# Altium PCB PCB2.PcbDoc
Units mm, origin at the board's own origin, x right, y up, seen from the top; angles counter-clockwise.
Board outline 200 x 200.6 mm, 2 copper layers (Top Layer, Bottom Layer); 120 components, 153 nets, 524 pads, 0 vias.
Unrouted connection lines stored in the file: 336.
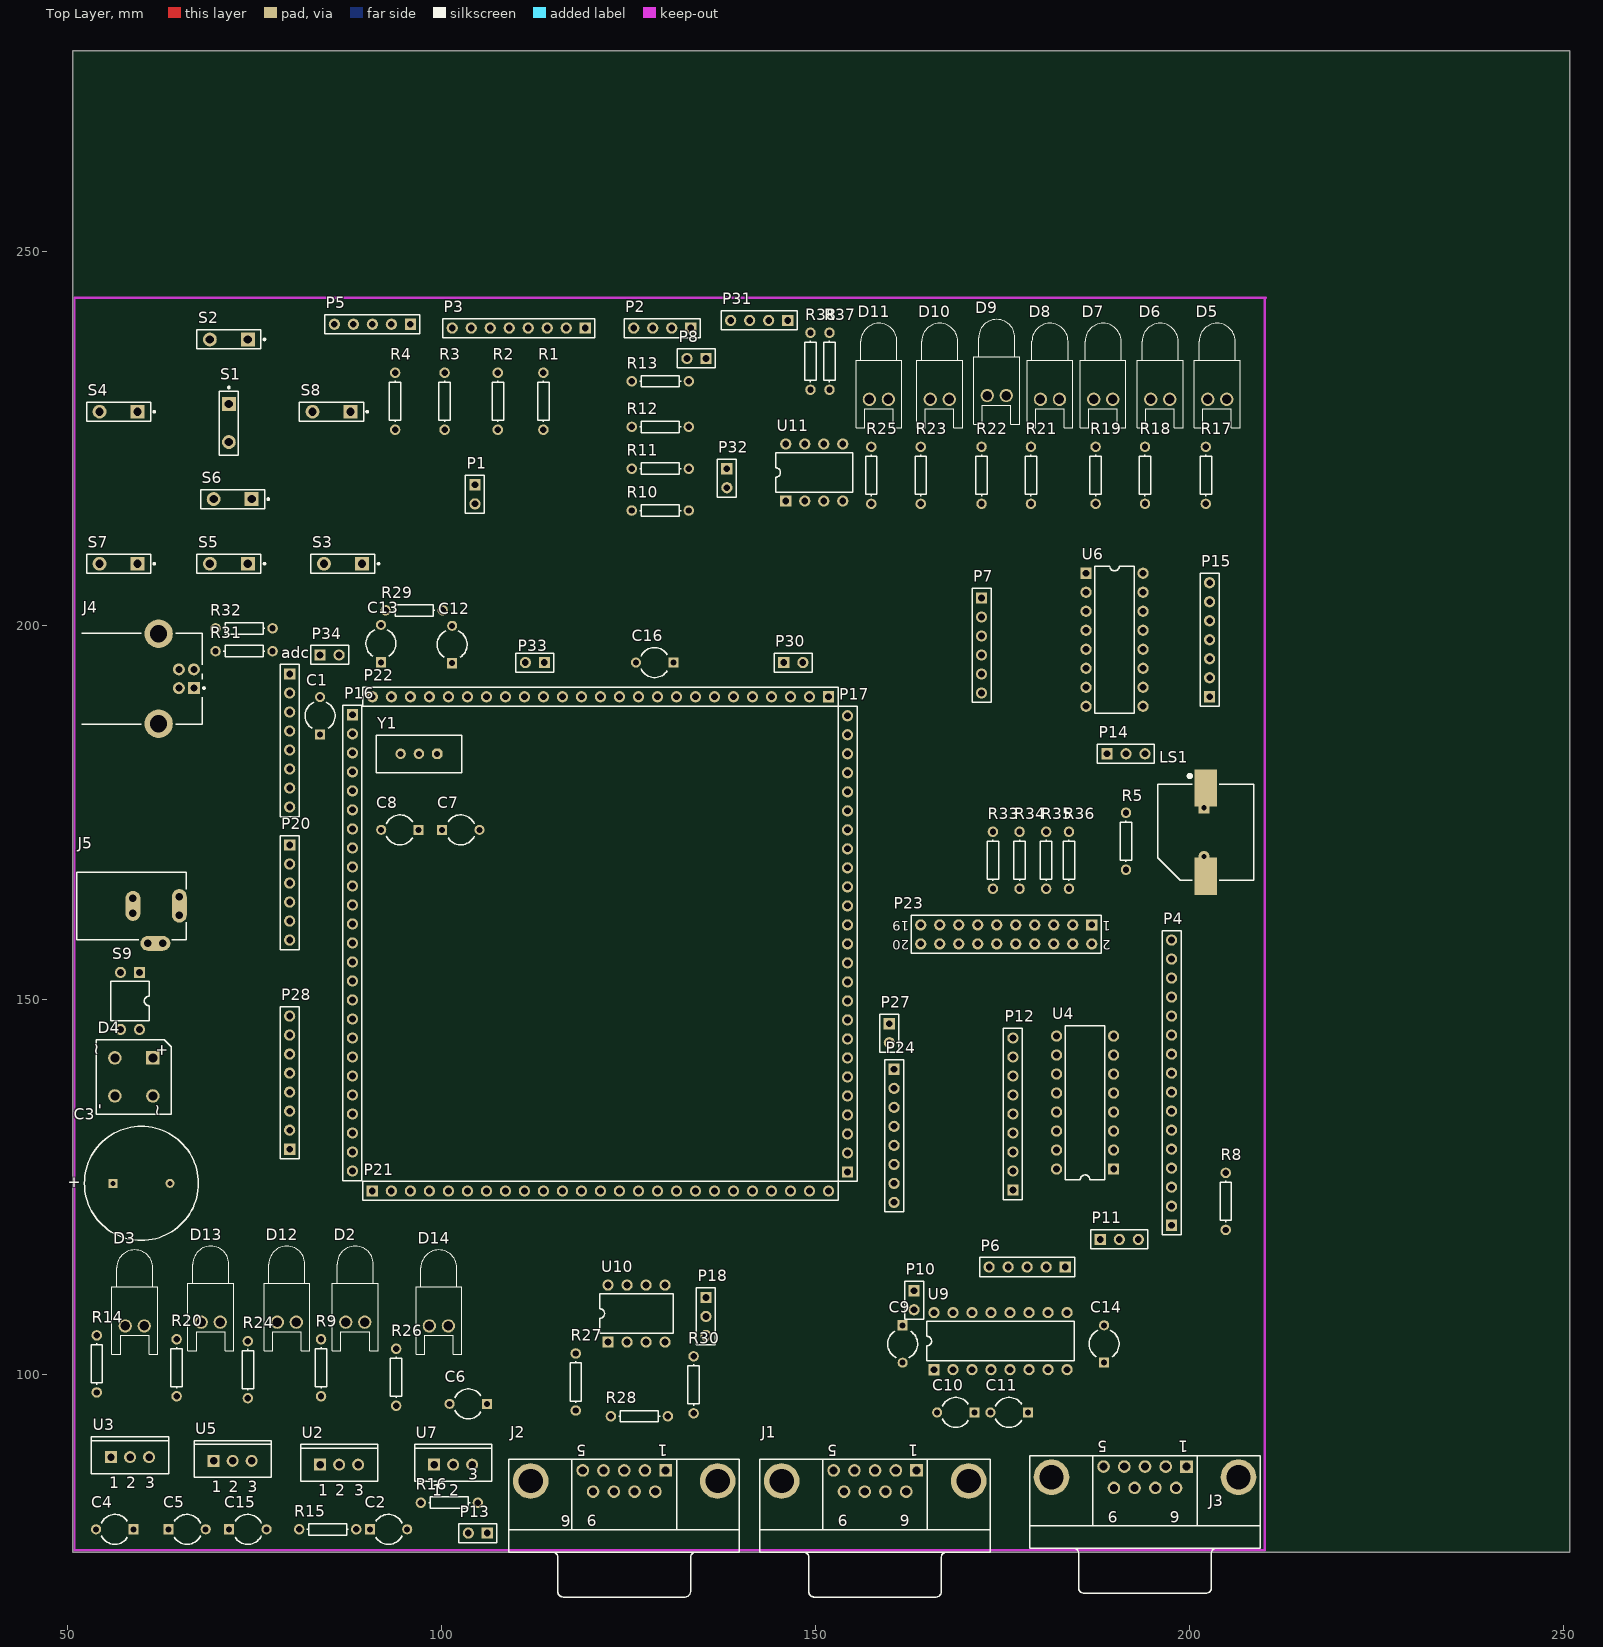
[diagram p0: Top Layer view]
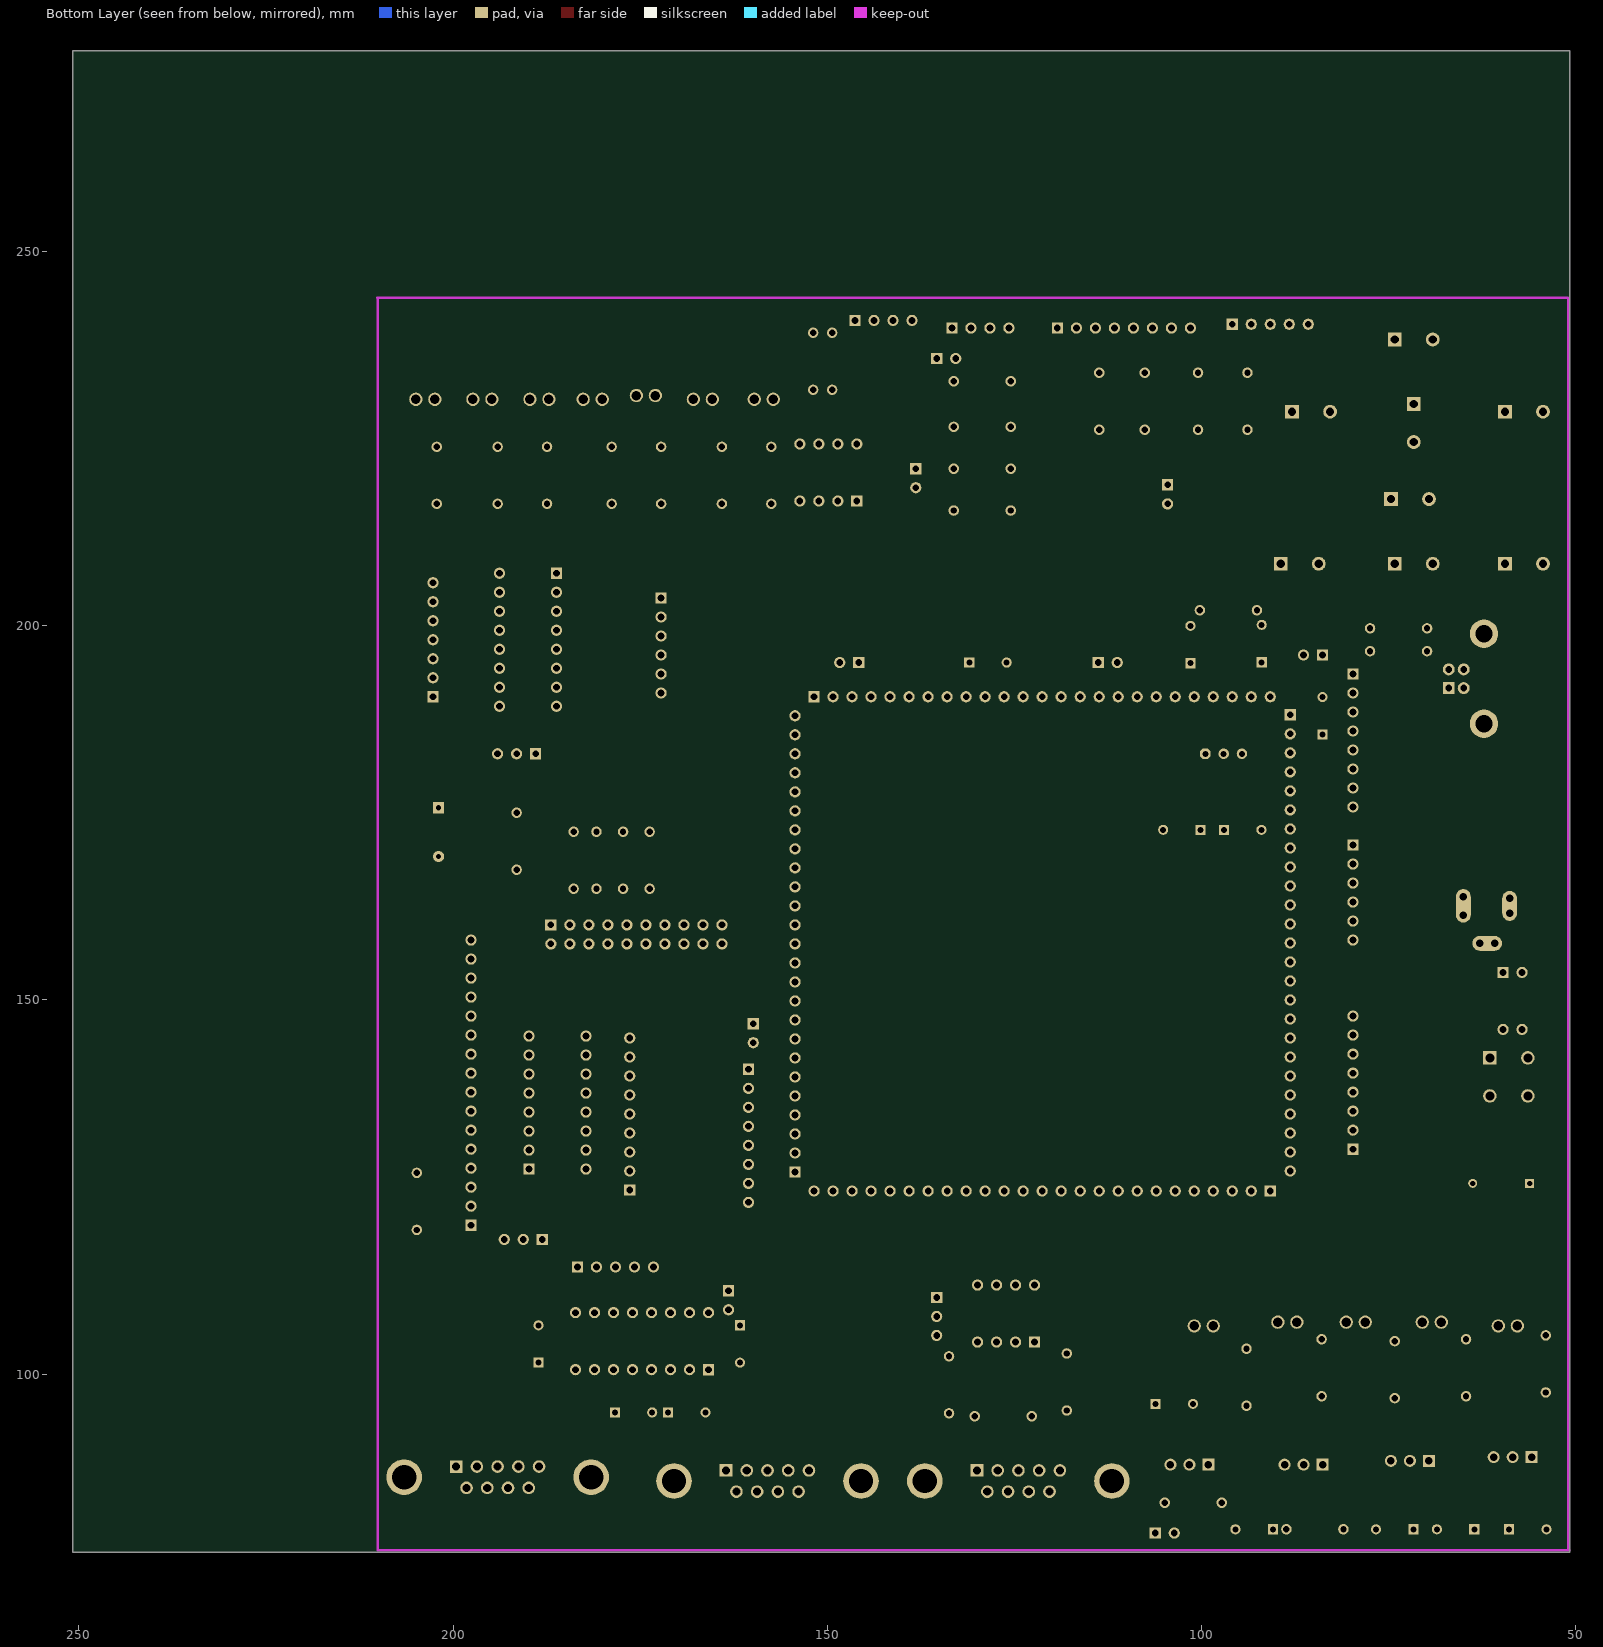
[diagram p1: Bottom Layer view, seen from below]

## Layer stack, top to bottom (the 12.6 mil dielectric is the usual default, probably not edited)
Top Layer: signal copper 0.0356
Dielectric: dielectric 0.32, FR-4, Dk 4.8
Bottom Layer: signal copper 0.0356

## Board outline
50.8,76.2 250.8,76.2 250.8,276.8 50.8,276.8

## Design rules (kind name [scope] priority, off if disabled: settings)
Clearance [All] p1: gap=0.2
PolygonConnect [All] p1: connectstyle=Relief reliefconductorwidth=0.254 reliefentries=4 polygonreliefangle="90 Angle"
RoomDefinition relevance [InComponentClass('relevance')] p1: confinementstyle=ConfineIn formatcopy=TRUE lockcomponents=FALSE outline 0,0 50.8,0 50.8,25.4 0,25.4
RoutingLayers [All] p1: top layer_v5=FALSE bottom layer_v5=TRUE
RoutingVias [All] p1: holewidth=0.2 width=2 viastyle="Through Hole" minholewidth=0.711 minwidth=1.27 maxholewidth=0.711 maxwidth=1.27
SilkscreenOverComponentPads [All] p1: minsilkscreentomaskgap=0.254
SolderMaskExpansion [All] p1: expansion=0.102
TestPointUsage [All] p1: valid=0 allowmultiple=FALSE
Testpoint [All] p1: side=15 testpointundercomponent=TRUE minsize=1.016 maxsize=2.54 preferedsize=1.524 minholesize=0 maxholesize=1.016 preferedholesize=0.813 testpointgrid=0.025 style=1023 order=0-112345678
Width [All] p1: maxlimit=0.2 minlimit=0.2 preferedwidth=0.2
22 further rules are at their usual default settings.

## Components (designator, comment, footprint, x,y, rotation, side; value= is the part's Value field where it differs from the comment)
adc "Header 8" HDR1X8 79.756,193.548 r270 top
C1 "Cap2" CAPR5-4X5 83.82,187.96 r90 top
C2 "Cap2" CAPR5-4X5 92.964,79.248 r0 top
C3 "Cap Pol1" RB7.6-15 59.944,125.476 r180 top
C4 "Cap2" CAPR5-4X5 56.388,79.248 r180 top
C5 "Cap2" CAPR5-4X5 66.04,79.248 r0 top
C6 "Cap2" CAPR5-4X5 103.632,96.012 r180 top
C7 "Cap2" CAPR5-4X5 102.616,172.72 r0 top
C8 "Cap2" CAPR5-4X5 94.488,172.72 r180 top
C9 "Cap2" CAPR5-4X5 161.671,104.013 r270 top
C10 "Cap2" CAPR5-4X5 168.783,94.869 r180 top
C11 "Cap2" CAPR5-4X5 175.895,94.869 r180 top
C12 "Cap2" CAPR5-4X5 101.473,197.485 r90 top
C13 "Cap2" CAPR5-4X5 91.948,197.612 r90 top
C14 "Cap2" CAPR5-4X5 188.595,104.013 r90 top
C15 "Cap2" CAPR5-4X5 74.168,79.248 r0 top
C16 "Cap2" CAPR5-4X5 128.524,195.072 r180 top
D2 "LED0" LED-0 88.519,106.934 r180 top
D3 "LED0" LED-0 59.055,106.426 r180 top
D4 "Bridge1" D-38 58.928,139.7 r270 top
D5 "LED0" LED-0 203.708,230.251 r180 top
D6 "LED0" LED-0 196.088,230.251 r180 top
D7 "LED0" LED-0 188.468,230.251 r180 top
D8 "LED0" LED-0 181.356,230.251 r180 top
D9 "LED0" LED-0 174.244,230.759 r180 top
D10 "LED0" LED-0 166.624,230.251 r180 top
D11 "LED0" LED-0 158.496,230.251 r180 top
D12 "LED0" LED-0 79.375,106.934 r180 top
D13 "LED0" LED-0 69.215,106.934 r180 top
D14 "LED0" LED-0 99.695,106.426 r180 top
J1 "D Connector 9" DSUB1.385-2H9 157.988,76.2 r180 top
J2 "D Connector 9" DSUB1.385-2H9 124.46,76.2 r180 top
J3 "D Connector 9" DSUB1.385-2H9 194.056,76.708 r180 top
J4 "1-1470156-1" 1-1470156 51.943,192.913 r180 top
J5 "PWR2.5" KLD-0202 51.308,162.56 r0 top
LS1 "Buzzer" ABSM-1574 202.184,178.308 r270 top
P1 "pad/sw" HDR1X2 104.521,218.821 r270 top
P2 "Debug Unit" HDR1X4 133.35,239.776 r180 top
P3 "keypad4*4" HDR1X8 119.253,239.776 r180 top
P4 "LCD2*16" HDR1X16 197.612,119.888 r90 top
P5 "Interrupt" HDR1X5 95.885,240.284 r180 top
P6 "Header 5" HDR1X5 183.388,114.3 r180 top
P7 "pwm" HDR1X6 172.212,203.708 r270 top
P8 "pad/sw" HDR1X2 135.382,235.712 r180 top
P10 "LIGHT on/off" HDR1X2 163.195,111.125 r270 top
P11 "lcd/7seg" HDR1X3 188.087,117.983 r0 top
P12 "7SEGMENT*2" HDR1X9 176.403,124.587 r90 top
P13 "Header 2" HDR1X2 106.172,78.74 r180 top
P14 "5v/12v" HDR1X3 188.976,182.88 r0 top
P15 "12/5 v . 500ma out" HDR1X7 202.692,190.5 r90 top
P16 "1-25" HDR1X25 88.138,188.087 r270 top
P17 "51-75" HDR1X25 154.305,127 r90 top
P18 "Header 3" HDR1X3 135.382,110.236 r270 top
P20 "Programmable Clock Output" HDR1X6 79.756,170.688 r270 top
P21 "26-50" HDR1X25 90.805,124.46 r0 top
P22 "76-100" HDR1X25 151.765,190.5 r180 top
P23 "Header 10X2" HDR2X10 186.944,160.02 r180 top
P24 "Synchronous Serial Controller" HDR1X8 160.528,140.716 r270 top
P27 "TST" HDR1X2 159.893,146.812 r270 top
P28 "Serial Peripheral Interface (SPI)" HDR1X8 79.756,130.048 r90 top
P30 "ERASE" HDR1X2 145.796,195.072 r0 top
P31 "2-wire" HDR1X4 146.304,240.792 r180 top
P32 "Header 2" HDR1X2 138.176,220.98 r270 top
P33 "JTAGSEL" HDR1X2 113.792,195.072 r180 top
P34 "Header 2" HDR1X2 83.82,196.088 r0 top
R1 "Res1" AXIAL-0.3 113.665,229.997 r270 top
R2 "Res1" AXIAL-0.3 107.569,229.997 r270 top
R3 "Res1" AXIAL-0.3 100.457,229.997 r270 top
R4 "Res1" AXIAL-0.3 93.853,229.997 r270 top
R5 "Res1" AXIAL-0.3 191.516,171.196 r90 top
R8 "Res1" AXIAL-0.3 204.851,123.063 r90 top
R9 "Res1" AXIAL-0.3 83.947,100.838 r90 top
R10 "Res1" AXIAL-0.3 129.286,215.392 r180 top
R11 "Res1" AXIAL-0.3 129.286,220.98 r180 top
R12 "Res1" AXIAL-0.3 129.286,226.568 r180 top
R13 "Res1" AXIAL-0.3 129.286,232.664 r180 top
R14 "Res1" AXIAL-0.3 53.975,101.346 r90 top
R15 "Res1" AXIAL-0.3 84.836,79.248 r0 top
R16 "Res1" AXIAL-0.3 101.092,82.804 r180 top
R17 "Res1" AXIAL-0.3 202.184,220.091 r90 top
R18 "Res1" AXIAL-0.3 194.056,220.091 r90 top
R19 "Res1" AXIAL-0.3 187.452,220.091 r90 top
R20 "Res1" AXIAL-0.3 64.643,100.838 r90 top
R21 "Res1" AXIAL-0.3 178.816,220.091 r90 top
R22 "Res1" AXIAL-0.3 172.212,220.091 r90 top
R23 "Res1" AXIAL-0.3 164.084,220.091 r90 top
R24 "Res1" AXIAL-0.3 74.168,100.584 r90 top
R25 "Res1" AXIAL-0.3 157.48,220.091 r90 top
R26 "Res1" AXIAL-0.3 93.98,99.568 r90 top
R27 "Res1" AXIAL-0.3 117.983,98.933 r90 top
R28 "Res1" AXIAL-0.3 126.492,94.361 r0 top
R29 "Res1" AXIAL-0.3 96.393,202.057 r180 top
R30 "Res1" AXIAL-0.3 133.731,98.552 r90 top
R31 "Res1" AXIAL-0.3 73.66,196.596 r0 top
R32 "Res1" AXIAL-0.3 73.66,199.644 r0 top
R33 "Res1" AXIAL-0.3 173.736,168.656 r90 top
R34 "Res1" AXIAL-0.3 177.292,168.656 r90 top
R35 "Res1" AXIAL-0.3 180.848,168.656 r90 top
R36 "Res1" AXIAL-0.3 183.896,168.656 r90 top
R37 "Res1" AXIAL-0.3 151.892,235.331 r90 top
R38 "Res1" AXIAL-0.3 149.352,235.331 r90 top
S1 "SW-PB" SPST-2 71.628,227.076 r270 top
S2 "SW-PB" SPST-2 71.628,238.252 r180 top
S3 "SW-PB" SPST-2 86.868,208.28 r180 top
S4 "SW-PB" SPST-2 56.896,228.6 r180 top
S5 "SW-PB" SPST-2 71.628,208.28 r180 top
S6 "SW-PB" SPST-2 72.136,216.916 r180 top
S7 "SW-PB" SPST-2 56.896,208.28 r180 top
S8 "SW-PB" SPST-2 85.344,228.6 r180 top
S9 "SW DIP-2" DIP-4 58.42,149.86 r180 top
U2 "LM317T" 221A-04 86.36,87.884 r0 top
U3 "MC78M12BT" 221A-04 58.42,88.9 r0 top
U4 "DM7447AN" N16E 186.055,136.271 r90 top
U5 "MC78M05CT" 221A-04 72.136,88.392 r0 top
U6 "ULN2003A" A16 189.992,198.12 r270 top
U7 "MC78M05CT" 221A-04 101.6,87.884 r0 top
U9 "MAX232ACPE" PE16A 174.752,104.394 r0 top
U10 "MCP2551-E/P" PDIP300-8 126.111,108.077 r0 top
U11 "ST24E256B6" PSDIP8A 149.86,220.472 r0 top
Y1 "ECS-49-20-4-3IL" HC-49US 97.028,182.88 r180 top

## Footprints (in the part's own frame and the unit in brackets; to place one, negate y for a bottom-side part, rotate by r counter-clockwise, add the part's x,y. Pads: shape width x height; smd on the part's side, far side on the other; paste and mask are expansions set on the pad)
1-1470156 [mm] "Connector; USB1.1, Type B, Thru-Hole; 4 Position; Right Angle"
  rect 1.6x1.6 hole 0.92: 1(-15.01,1.25)
  round 1.6 hole 0.92: 2(-15.01,-1.25) 3(-13.01,-1.25) 4(-13.01,1.25)
  round 3.8 hole 2.3: 5(-10.3,6.02) 6(-10.3,-6.02)
  silkscreen extent -16.49,-6.05 -0.02,6.05
221A-04 [mm] "TO, Thru-Hole, Vertical, Heatsink Mounted; 3 In-Line Leads; Pitch 2.54 mm"
  rect 1.6x1.6 hole 1: 1(-2.54,0)
  round 1.6 hole 1: 2(0,0) 3(2.54,0)
  silkscreen extent -5.15,-2.2 5.15,2.7
A16 [mm] "DIP; 16 Leads; Row Spacing 7.62 mm; Pitch 2.54 mm"
  rect 1.5x1.5 hole 0.9: 1(-8.89,-3.81)
  round 1.5 hole 0.9: 2(-6.35,-3.81) 3(-3.81,-3.81) 4(-1.27,-3.81) 5(1.27,-3.81) 6(3.81,-3.81) 7(6.35,-3.81) 8(8.89,-3.81) 9(8.89,3.81) 10(6.35,3.81) 11(3.81,3.81) 12(1.27,3.81) 13(-1.27,3.81) 14(-3.81,3.81) 15(-6.35,3.81) 16(-8.89,3.81)
  silkscreen extent -9.85,-2.65 9.85,2.65
ABSM-1574 [mm] "Magnetic Transducer Buzzer"
  rect 5x3 smd: 1(0,0) 2(11.8,0)
  rect 1.5x1.5 hole 0.7: 1A(2.65,-0.24)
  round 1.5 hole 0.7: 2A(9.15,-0.24)
  silkscreen extent -1.83,-6.4 12.3,6.4
AXIAL-0.3 [mm] "Resistor; 2 Leads"
  round 1.4 hole 0.85: 1(-3.81,0) 2(3.81,0)
  silkscreen extent -2.77,-0.76 2.77,0.76
CAPR5-4X5 [mm] "Capacitor; 2 Leads"
  rect 1.35x1.35 hole 0.8: 1(-2.5,0)
  round 1.35 hole 0.8: 2(2.5,0)
  silkscreen extent -1.69,-2 1.82,2
D-38 [mm] "Bridge Rectifier; 4 Terminals; Body 9.4 x 9.4 mm (typ); Pitch 5.08 mm"
  rect 1.8x1.8 hole 1.2: 1(-2.54,2.54)
  round 1.8 hole 1.2: 2(-2.54,-2.54) 3(2.54,-2.54) 4(2.54,2.54)
  silkscreen extent -5,-5 5,5
DIP-4 [mm] "DIP; 4 Leads; Row Spacing 7.62 mm; Pitch 2.54 mm"
  rect 1.5x1.5 hole 0.9: 1(-1.27,-3.81)
  round 1.5 hole 0.9: 2(1.27,-3.81) 3(1.27,3.81) 4(-1.27,3.81)
  silkscreen extent -2.55,-2.65 2.55,2.65
DSUB1.385-2H9 [mm] "Connector; D Subminiature; 9 Position; Right Angle; Pitch 1.385 mm"
  rect 1.69x1.69 hole 1.09: 1(-5.54,-10.92)
  round 1.69 hole 1.09: 2(-2.77,-10.92) 3(0,-10.92) 4(2.77,-10.92) 5(5.54,-10.92) 6(-4.155,-8.08) 7(-1.385,-8.08) 8(1.385,-8.08) 9(4.155,-8.08)
  round 4.76 hole 3.26: 10(-12.495,-9.5) 11(12.495,-9.5)
  silkscreen extent -15.4,-12.4 15.4,6
HC-49US [mm] "Quartz Crystal, Thru-Hole; 3 Leads; Body 11.35 x 5 x 3.5 mm (LxWxH max)"
  oct 1.4x1.4 hole 0.8: 1(-2.44,0)
  round 1.4 hole 0.8: 2(0,0) 3(2.44,0)
  silkscreen extent -5.7,-2.5 5.7,2.5
HDR1X2 [mm] "Connector; Header; 2 Position"
  rect 1.5x1.5 hole 0.9: 1(0,0)
  round 1.5 hole 0.9: 2(2.54,0)
  silkscreen extent -1.27,-1.27 3.81,1.27
HDR1X3 [mm] "Connector; Header; 3 Position"
  rect 1.5x1.5 hole 0.9: 1(0,0)
  round 1.5 hole 0.9: 2(2.54,0) 3(5.08,0)
  silkscreen extent -1.27,-1.27 6.35,1.27
HDR1X4 [mm] "Connector; Header; 4 Position"
  rect 1.5x1.5 hole 0.9: 1(0,0)
  round 1.5 hole 0.9: 2(2.54,0) 3(5.08,0) 4(7.62,0)
  silkscreen extent -1.27,-1.27 8.89,1.27
HDR1X5 [mm] "Connector; Header; 5 Position"
  rect 1.5x1.5 hole 0.9: 1(0,0)
  round 1.5 hole 0.9: 2(2.54,0) 3(5.08,0) 4(7.62,0) 5(10.16,0)
  silkscreen extent -1.27,-1.27 11.43,1.27
HDR1X6 [mm] "Connector; Header; 6 Position"
  rect 1.5x1.5 hole 0.9: 1(0,0)
  round 1.5 hole 0.9: 2(2.54,0) 3(5.08,0) 4(7.62,0) 5(10.16,0) 6(12.7,0)
  silkscreen extent -1.27,-1.27 13.97,1.27
HDR1X7 [mm] "Connector; Header; 7 Position"
  rect 1.5x1.5 hole 0.9: 1(0,0)
  round 1.5 hole 0.9: 2(2.54,0) 3(5.08,0) 4(7.62,0) 5(10.16,0) 6(12.7,0) 7(15.24,0)
  silkscreen extent -1.27,-1.27 16.51,1.27
HDR1X8 [mm] "Connector; Header; 8 Position"
  rect 1.5x1.5 hole 0.9: 1(0,0)
  round 1.5 hole 0.9: 2(2.54,0) 3(5.08,0) 4(7.62,0) 5(10.16,0) 6(12.7,0) 7(15.24,0) 8(17.78,0)
  silkscreen extent -1.27,-1.27 19.05,1.27
HDR1X9 [mm] "Connector; Header; 9 Position"
  rect 1.5x1.5 hole 0.9: 1(0,0)
  round 1.5 hole 0.9: 2(2.54,0) 3(5.08,0) 4(7.62,0) 5(10.16,0) 6(12.7,0) 7(15.24,0) 8(17.78,0) 9(20.32,0)
  silkscreen extent -1.27,-1.27 21.59,1.27
HDR1X16 [mm] "Connector; Header; 16 Position"
  rect 1.5x1.5 hole 0.9: 1(0,0)
  round 1.5 hole 0.9: 2(2.54,0) 3(5.08,0) 4(7.62,0) 5(10.16,0) 6(12.7,0) 7(15.24,0) 8(17.78,0) 9(20.32,0) 10(22.86,0) 11(25.4,0) 12(27.94,0) 13(30.48,0) 14(33.02,0) 15(35.56,0) 16(38.1,0)
  silkscreen extent -1.27,-1.27 39.37,1.27
HDR1X25 [mm] "Connector; Header; 25 Position"
  rect 1.5x1.5 hole 0.9: 1(0,0)
  round 1.5 hole 0.9: 2(2.54,0) 3(5.08,0) 4(7.62,0) 5(10.16,0) 6(12.7,0) 7(15.24,0) 8(17.78,0) 9(20.32,0) 10(22.86,0) 11(25.4,0) 12(27.94,0) 13(30.48,0) 14(33.02,0) 15(35.56,0) 16(38.1,0) 17(40.64,0) 18(43.18,0) 19(45.72,0) 20(48.26,0) 21(50.8,0) 22(53.34,0) 23(55.88,0) 24(58.42,0) 25(60.96,0)
  silkscreen extent -1.27,-1.27 62.23,1.27
HDR2X10 [mm] "Connector; Header; 10x2 Position"
  rect 1.5x1.5 hole 0.9: 1(0,0)
  round 1.5 hole 0.9: 2(0,2.54) 3(2.54,0) 4(2.54,2.54) 5(5.08,0) 6(5.08,2.54) 7(7.62,0) 8(7.62,2.54) 9(10.16,0) 10(10.16,2.54) 11(12.7,0) 12(12.7,2.54) 13(15.24,0) 14(15.24,2.54) 15(17.78,0) 16(17.78,2.54) 17(20.32,0) 18(20.32,2.54) 19(22.86,0) 20(22.86,2.54)
  silkscreen extent -1.27,-1.27 24.13,3.81
KLD-0202 [mm] "DC Power Jack, 2.5mm, KLD Series, PCB Mount"
  oval 2x4.5 all layers, no hole: 1(13.7,0)
  round 1.5 hole 1: 1A(13.7,-1.25) 1B(13.7,1.25) 2A(7.5,-1) 2B(7.5,1) 3A(9.5,-5) 3B(11.5,-5)
  oval 2x4 all layers, no hole: 2(7.5,0)
  oval 4x2 all layers, no hole: 3(10.5,-5)
  silkscreen extent 0,-4.5 14.6,4.5
LED-0 [mil] "Typical INFRARED GaAs LED; 2 Leads"
  round 70 hole 50: 1(50,0) 2(-50,0)
  silkscreen extent -120,-400 120,150
N16E [mm] "DIP; 16 Leads; Row Spacing 7.62 mm; Pitch 2.54 mm"
  rect 1.5x1.5 hole 0.9: 1(-8.89,-3.81)
  round 1.5 hole 0.9: 2(-6.35,-3.81) 3(-3.81,-3.81) 4(-1.27,-3.81) 5(1.27,-3.81) 6(3.81,-3.81) 7(6.35,-3.81) 8(8.89,-3.81) 9(8.89,3.81) 10(6.35,3.81) 11(3.81,3.81) 12(1.27,3.81) 13(-1.27,3.81) 14(-3.81,3.81) 15(-6.35,3.81) 16(-8.89,3.81)
  silkscreen extent -10.3,-2.65 10.3,2.65
PDIP300-8 [mm] "DIP, Plastic; 8 Leads; Row Spacing 7.62 mm; Pitch 2.54 mm"
  rect 1.5x1.5 hole 0.9: 1(-3.81,-3.81)
  round 1.5 hole 0.9: 2(-1.27,-3.81) 3(1.27,-3.81) 4(3.81,-3.81) 5(3.81,3.81) 6(1.27,3.81) 7(-1.27,3.81) 8(-3.81,3.81)
  silkscreen extent -4.9,-2.65 4.9,2.65
PE16A [mm] "DIP; 16 Leads; Row Spacing 7.62 mm; Pitch 2.54 mm"
  rect 1.5x1.5 hole 0.9: 1(-8.89,-3.81)
  round 1.5 hole 0.9: 2(-6.35,-3.81) 3(-3.81,-3.81) 4(-1.27,-3.81) 5(1.27,-3.81) 6(3.81,-3.81) 7(6.35,-3.81) 8(8.89,-3.81) 9(8.89,3.81) 10(6.35,3.81) 11(3.81,3.81) 12(1.27,3.81) 13(-1.27,3.81) 14(-3.81,3.81) 15(-6.35,3.81) 16(-8.89,3.81)
  silkscreen extent -9.85,-2.65 9.85,2.65
PSDIP8A [mm] "DIP; 8 Leads; Row Spacing 7.62 mm; Pitch 2.54 mm"
  rect 1.5x1.5 hole 0.9: 1(-3.81,-3.81)
  round 1.5 hole 0.9: 2(-1.27,-3.81) 3(1.27,-3.81) 4(3.81,-3.81) 5(3.81,3.81) 6(1.27,3.81) 7(-1.27,3.81) 8(-3.81,3.81)
  silkscreen extent -5.15,-2.65 5.15,2.65
RB7.6-15 [mm] "Polarized Capacitor (Radial); 2 Leads"
  rect 1.2x1.2 hole 0.7: 1(3.81,0)
  round 1.2 hole 0.7: 2(-3.81,0)
  silkscreen extent -7.62,-7.62 7.62,7.62
SPST-2 [mm] "Circuit Breaker; 2 Leads"
  rect 1.85x1.85 hole 1.1: 1(-2.54,0)
  round 1.85 hole 1.1: 2(2.54,0)
  silkscreen extent -4.89,-1.27 4.28,1.27

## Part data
adc: "Header, 8-Pin"
C1 C2 C4 C5 C6 C7 C8 C9 C10 C11 C12 C13 C14 C15 C16: "Capacitor"
C3: "Polarized Capacitor (Radial)"
D2 D3 D5 D6 D7 D8 D9 D10 D11 D12 D13 D14: "Typical INFRARED GaAs LED"
D4: "Full Wave Diode Bridge"
J1 J2 J3: "Receptacle Assembly, 9 Position, Right Angle"
J4: "USB 1.1, Right Angle, Thru-Hole, B Type, Receptacle, 4 Position, White"
J5: "Low Voltage Power Supply Connector"
LS1: "Magnetic Transducer Buzzer"
P1 P8 P10 P27 P30 P33: library part "Header 2", "Header, 2-Pin"
P2 P31: library part "Header 4", "Header, 4-Pin"
P3 P24 P28: library part "Header 8", "Header, 8-Pin"
P4: library part "Header 16", "Header, 16-Pin"
P5: library part "Header 5", "Header, 5-Pin"
P6: "Header, 5-Pin"
P7 P20: library part "Header 6", "Header, 6-Pin"
P11 P14: library part "Header 3", "Header, 3-Pin"
P12: library part "Header 9", "Header, 9-Pin"
P13 P32 P34: "Header, 2-Pin"
P15: library part "Header 7", "Header, 7-Pin"
P16 P17 P21 P22: library part "Header 25", "Header, 25-Pin"
P18: "Header, 3-Pin"
P23: "Header, 10-Pin, Dual row"
R1 R2 R3 R4 R5 R8 R9 R10 R11 R12 R13 R14 R15 R16 R17 R18 R19 R20 R21 R22 R23 R24 R25 R26 R27 R28 R29 R30 R31 R32 R33 R34 R35 R36 R37 R38: "Resistor"
S1 S2 S3 S4 S5 S6 S7 S8: "Switch"
S9: "DIP Switch, 2 Position, SPST"
U2: "3-Terminal Adjustable Positive Voltage Regulator"
U3 U5 U7: "3-Terminal Medium-Current Positive Fixed Voltage Regulator"
U4: "BCD to 7-Segment Decoder/Driver"
U6: "High-Voltage, High-Current Darlington Array"
U9: "+5V Powered, Multi-Channel RS-232 Driver/Receiver"
U10: "High Speed CAN Transceiver, 8-Pin Plastic DIP, Extended Grade"
U11: "Serial Access Extended Addressing Compatible with I²C Bus 256K (32K x 8) EEPROM"
Y1: "Crystal Oscillator, 3rd In-Line Lead Version"

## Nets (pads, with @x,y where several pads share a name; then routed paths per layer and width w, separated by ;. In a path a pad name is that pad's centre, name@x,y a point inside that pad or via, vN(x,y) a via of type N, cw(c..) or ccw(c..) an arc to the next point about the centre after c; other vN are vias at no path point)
5V: C5.1 P14.1 R24.1 U5.3
12V: C4.1 R20.1 U3.3
+12: P14.3
A: P12.5 U4.13
AD4: adc.4 P16.3
AD5: adc.3 P16.4
AD6: adc.2 P16.5
AD7: adc.1 P16.6
ADVREF: C1.2 P16.1 P34.2
B: P12.6 U4.12
C: P12.7 U4.11
D: P12.8 U4.10
DB4: P4.11 P20.2 P21.15 U4.7
DB5: P4.12 P21.16 U4.1
DB6: P4.13 P21.17 U4.2
DB7: P4.14 P21.18 R5.1 U4.6
DCD1: P7.2 P17.19 R18.1 U6.2
DDM: P22.18 R32.2
DDP: P22.19 R31.2
DSR1: P17.20 R17.1 U6.1
DTR1: P17.21
E: P4.6 P12.1 P12.9 P21.20 U4.9
ERASE: P22.17 P33.2
F: P12.3 U4.15
FIQ: P3.5 P5.3 P17.25 R1.1 S4.1
G: P12.4 U4.14
GND: C1.1 C2.2 C3.2 C4.2 C5.2 C6.2 C7.1 C8.1 C9.1 C12.1 C13.1 C15.1 C16.1 D2.2 D3.2 D4.1 D5.2 D6.2 D7.2 D8.2 D9.2 D10.2 D11.2 D12.2 D13.2 D14.2 J1.5 J1.10 J1.11 J2.6 J2.10 J2.11 J3.5 J3.10 J3.11 J4.4 J4.5 J4.6 LS1.2 LS1.2A P2.4 P4.1 P4.5 P4.16 P5.5 P6.3 P7.6 P8.2 P13.2 P16.2 P16.16 P17.2 P17.18 P18.1 P20.6 P21.7 P22.8 P22.21 P23.4 P23.6 P23.8 P23.10 P23.12 P23.14 P23.16 P23.18 P23.20 P24.1 P28.1 P31.4 R8.2 R15.1 R16.1 R28.2 R30.1 S1.2 S2.2 S3.2 S4.2 U3.2 U4.8 U5.2 U6.8 U7.2 U9.15 U10.2 U11.1 U11.2 U11.3 U11.4 U11.7 Y1.2
IRQ0: P3.2 P5.4 P16.22 P28.3 R12.2 S7.1
IRQ1: P3.8 P5.2 P22.5 R4.1 S1.1
JTAGSEL: P22.2 P30.2
KBD1: P2.3 P3.7 P17.23 P20.5 R3.1 S2.1
KBD2: P2.2 P3.6 P17.24 R2.1 S3.1
KBD4: P3.4 P16.20 P28.5 R10.2 S5.1
KBD5: P3.3 P16.21 P28.4 R11.2 S6.1
KBD7: P3.1 P16.23 P28.2 R13.2 S8.1
LED0: P17.13 R25.1 U6.7
LED1: P17.14 R23.1 U6.6
LED2: P7.5 P17.15 R22.1 U6.5
LED3: P7.4 P17.16 R21.1 U6.4
LED4: P7.3 P17.17 R19.1 U6.3
MISO: P16.24 P28.7
MOSI: P16.25 P28.8
NetC6_1: C6.1 P13.1 R26.1 U7.3
NetC9_2: C9.2 U9.2
NetC10_1: C10.1 U9.3
NetC10_2: C10.2 U9.1
NetC11_1: C11.1 U9.5
NetC11_2: C11.2 U9.4
NetC12_2: C12.2 R29.1
NetC14_1: C14.1 U9.6
NetD2_1: D2.1 R9.2
NetD3_1: D3.1 R14.2
NetD4_2: D4.2 S9.3
NetD4_4: D4.4 S9.4
NetD5_1: D5.1 R17.2
NetD6_1: D6.1 R18.2
NetD7_1: D7.1 R19.2
NetD8_1: D8.1 R21.2
NetD9_1: D9.1 R22.2
NetD10_1: D10.1 R23.2
NetD11_1: D11.1 R25.2
NetD12_1: D12.1 R24.2
NetD13_1: D13.1 R20.2
NetD14_1: D14.1 R26.2
NetJ1_2: J1.2 U9.14
NetJ1_3: J1.3 U9.13
NetJ2_2: J2.2 U10.6
NetJ2_7: J2.7 U10.7
NetJ2_8: J2.8 R28.1
NetJ2_9: J2.9 R27.1
NetJ3_2: J3.2 U9.7
NetJ3_3: J3.3 U9.8
NetJ4_2: J4.2 R31.1
NetJ4_3: J4.3 R32.1
NetJ5_1: J5.1 J5.1A J5.1B S9.1
NetJ5_2: J5.2 J5.2A J5.2B J5.3 J5.3A J5.3B S9.2
NetLS1_1: LS1.1 LS1.1A R5.2
NetP1_2: P1.2 R1.2 R2.2 R3.2 R4.2
NetP4_2: P4.2 P11.3
NetP4_3: P4.3 R8.1
NetP4_15: P4.15 P10.1
NetP8_1: P8.1 R10.1 R11.1 R12.1 R13.1
NetP11_1: P11.1 U4.16
NetP14_2: P14.2 U6.9
NetP15_1: P15.1 U6.10
NetP15_2: P15.2 U6.11
NetP15_3: P15.3 U6.12
NetP15_4: P15.4 U6.13
NetP15_5: P15.5 U6.14
NetP15_6: P15.6 U6.15
NetP15_7: P15.7 U6.16
NetP18_2: P18.2 R30.2 U10.8
NetP23_3: P23.3 R36.1
NetP23_5: P23.5 R35.1
NetP23_9: P23.9 P23.11 R33.1
NetP27_1: P27.1 P30.1 P33.1
NetP32_1: P32.1 U11.8
NetR15_2: R15.2 U2.1
NRST: P17.7 P23.15
PA0/PGMEN0/RXD0: P6.5 P22.6 U9.12
PA1/PGMEN1/TXD0: P6.4 P22.7 U9.11
"PA2 3/PGMD11/TD": P17.5 P24.6
PA2/SCK0: P22.11
PA3/RTS0: P22.10
PA4/PGMNCMD/CTS0: P22.13
"PA5/PGMRDY/RX D 1": P6.1 P22.14 U9.9
"PA6/PGMNOE/T X D1": P6.2 P22.15 U9.10
PA8/PGMM0/RTS1: P16.13
PA9/PGMM1/CTS1: P16.14
"PA10/PGMM2/TW D": P16.18 P31.2 R37.1 U11.5
"PA11/PGMM3/TW CK": P16.19 P31.3 R38.1 U11.6
PA18/PGMD6/SPI0_SPCK: P21.1 P28.6
PA19/PGMD7/CANRX: P21.21 U10.4
PA20/PGMD8/CANTX: P21.22 U10.1
PA21/PGMD9/TF: P21.24 P24.8
PA22/PGMD10/TK: P21.25 P24.7
PA24/PGMD12/RD: P17.6 P24.5
PA25/PGMD13/RK: P17.9 P24.4
PA26/PGMD14/RF: P17.10 P24.3
PB4/ECRS: P17.4
PB5/ERX0: P21.9
PB6/ERX1: P21.6
PB7/ERXER: P21.13
PB8/EMDC: P21.3
PB9/EMDIO: P21.2
PB10/ETX2: P4.4 P12.2 P21.19
PB12/ETXER: P21.14
PB13/ERX2: P21.5
PB14/ERX3: P21.4
PB15/ERXDV/ECRSDV: P21.10
PB16/ECOL: P17.3
PB17/ERXCK: P21.11
PB26/TIOB1: P17.22
PB27/AD0/TIOA2: adc.8 P16.9
PB28/AD1/TIOB2: adc.7 P16.10
PB29/AD2/PCK1: adc.6 P16.11 P20.3
PB30/AD3/PCK2: adc.5 P16.12 P20.4
PLLRC: C13.2 P22.24 R29.2
TCK: P22.4
TDI: P17.1
TDO: P22.1 P23.13
TMS: P22.3 P23.7 R34.1
TST: P17.8 P27.2
VCC: C2.1 C14.2 C15.2 J4.1 P1.1 P2.1 P5.1 P7.1 P10.2 P11.2 P18.3 P20.1 P23.1 P23.2 P24.2 P31.1 P32.2 P34.1 R9.1 R16.2 R27.2 R33.2 R34.2 R35.2 R36.2 R37.2 R38.2 S5.2 S6.2 S7.2 S8.2 U2.2 U9.16 U10.3
VDDCORE: C16.2 P16.15 P17.12 P21.12 P22.12
VDDFLASH: P22.20
VDDIN: P16.8
VDDIO: P16.17 P17.11 P21.8 P21.23 P22.9
VDDOUT: P16.7
VDDPLL: P22.25
VIN: C3.1 D4.3 R14.1 U2.3 U3.1 U5.1 U7.1
XIN/PGMCK: C7.2 P22.22 Y1.1
XOUT: C8.2 P22.23 Y1.3
pads on no net: J1.1 J1.4 J1.6 J1.7 J1.8 J1.9 J2.1 J2.3 J2.4 J2.5 J3.1 J3.4 J3.6 J3.7 J3.8 J3.9 P4.7 P4.8 P4.9 P4.10 P22.16 P23.17 P23.19 U4.3 U4.4 U4.5 U10.5

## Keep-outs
Keep-Out Layer:
  lines w0.3: 50.844,76.454 210.058,76.454 210.058,243.713 ; 51,76.4 51,243.84 210.185,243.84

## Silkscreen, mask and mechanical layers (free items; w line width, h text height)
Drill Drawing:
  text ".LEGEND" at 255.88,81.28 h1.52
  text "Drill Drawing." at 255.88,78.74 h1.52

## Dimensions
50.844,76.454 to 218.44,75.946 on Mechanical 1
51,76.4 to 51,243.84 on Mechanical 1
